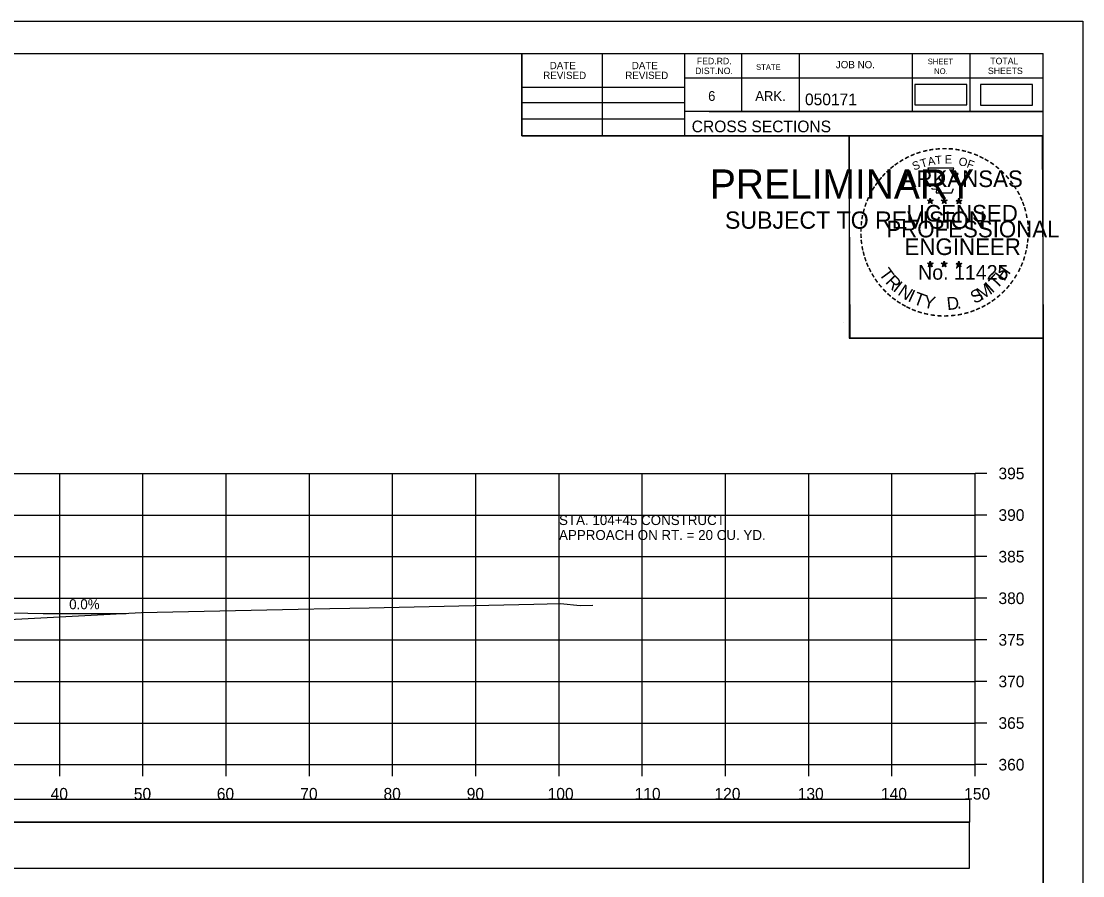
# Model space of a CAD drawing. Extents: x -37291014 to -37290680, y -936053 to -933067.
# Drawn here: x -37290807.7 to -37290680.2, y -935089.3 to -934986.6 of the extents above; entities that cross this region are included whole.
import ezdxf

# ---------------------------------------------------------------- set-up
doc = ezdxf.new("R2010")
doc.units = 0
for name, color, linetype in [('Default', 7, 'Continuous'), ('R_Axis', 7, 'Continuous'), ('R_Axis Annot', 7, 'Continuous'), ('R_Border', 7, 'Continuous'), ('R_Border PE', 7, 'Continuous'), ('R_Border Prem', 7, 'Continuous'), ('R_Drive', 7, 'Continuous'), ('R_Exist Surface', 7, 'Continuous'), ('R_Grid', 7, 'Continuous'), ('R_No Plot', 7, 'Continuous'), ('R_Water Annot', 7, 'Continuous'), ('R_Xsect Elev', 7, 'Continuous')]:
    doc.layers.add(name, color=color, linetype=linetype)

msp = doc.modelspace()

# ---------------------------------------------------------------- linework, layer by layer
at = {"layer": 'Default'}
for points in [[(-37290700.35, -934996.68), (-37290694.1, -934996.68), (-37290694.1, -934994.21), (-37290700.35, -934994.21)], [(-37290692.46, -934996.69), (-37290686.21, -934996.69), (-37290686.21, -934994.21), (-37290692.46, -934994.21)], [(-37290992.48, -935082.88), (-37290693.72, -935082.88), (-37290693.72, -935080.17), (-37290992.48, -935080.17)], [(-37290992.54, -935088.4), (-37290693.78, -935088.4), (-37290693.78, -935082.88), (-37290992.54, -935082.88)]]:
    msp.add_lwpolyline(points, close=True, dxfattribs=at)
at = {"layer": 'R_Axis'}
for p, q in [((-37290693.1, -935075.97), (-37290693.1, -935040.97)), ((-37290691.7, -935040.97), (-37290693.1, -935040.97)), ((-37290691.7, -935045.97), (-37290693.1, -935045.97)), ((-37290691.7, -935050.97), (-37290693.1, -935050.97)), ((-37290691.7, -935055.97), (-37290693.1, -935055.97)), ((-37290691.7, -935060.97), (-37290693.1, -935060.97)), ((-37290691.7, -935065.97), (-37290693.1, -935065.97)), ((-37290691.7, -935070.97), (-37290693.1, -935070.97)), ((-37290993.1, -935075.97), (-37290693.1, -935075.97)), ((-37290803.1, -935077.37), (-37290803.1, -935075.97)), ((-37290793.1, -935077.37), (-37290793.1, -935075.97)), ((-37290783.1, -935077.37), (-37290783.1, -935075.97)), ((-37290773.1, -935077.37), (-37290773.1, -935075.97)), ((-37290763.1, -935077.37), (-37290763.1, -935075.97)), ((-37290753.1, -935077.37), (-37290753.1, -935075.97)), ((-37290743.1, -935077.37), (-37290743.1, -935075.97)), ((-37290733.1, -935077.37), (-37290733.1, -935075.97)), ((-37290723.1, -935077.37), (-37290723.1, -935075.97)), ((-37290713.1, -935077.37), (-37290713.1, -935075.97)), ((-37290703.1, -935077.37), (-37290703.1, -935075.97)), ((-37290693.1, -935077.37), (-37290693.1, -935075.97)), ((-37290691.7, -935075.97), (-37290693.1, -935075.97))]:
    msp.add_line(p, q, dxfattribs=at)
at = {"layer": 'R_Border'}
for p, q in [((-37291001.1, -934990.51), (-37290684.92, -934990.51)), ((-37290747.56, -935000.39), (-37290747.56, -934990.51)), ((-37290737.88, -935000.39), (-37290737.88, -934990.51)), ((-37290728.02, -934990.51), (-37290728.02, -935000.39)), ((-37290721.18, -934990.51), (-37290721.18, -934997.45)), ((-37290714.24, -934990.51), (-37290714.24, -934997.45)), ((-37290700.66, -934990.51), (-37290700.66, -934997.45)), ((-37290693.72, -934990.51), (-37290693.72, -934997.45)), ((-37290684.92, -935195.97), (-37290684.92, -934990.51)), ((-37290747.56, -934994.53), (-37290728.02, -934994.53)), ((-37290684.92, -934993.45), (-37290728.02, -934993.45)), ((-37290684.92, -934993.43), (-37290684.92, -934993.43)), ((-37290747.56, -934996.39), (-37290728.02, -934996.39)), ((-37290747.56, -934998.33), (-37290728.02, -934998.33)), ((-37290684.92, -934997.45), (-37290728.02, -934997.45)), ((-37290725.06, -934997.45), (-37290684.92, -934997.45)), ((-37290684.92, -935000.39), (-37290747.56, -935000.39))]:
    msp.add_line(p, q, dxfattribs=at)
at = {"layer": 'R_Border PE'}
for p, q in [((-37290698.84, -935008.14), (-37290698.49, -935008.25)), ((-37290698.84, -935008.14), (-37290698.58, -935008.18)), ((-37290698.84, -935008.14), (-37290698.6, -935008.26)), ((-37290698.7, -935008.54), (-37290698.49, -935008.25)), ((-37290698.7, -935008.54), (-37290698.58, -935008.3)), ((-37290698.7, -935008.54), (-37290698.49, -935008.33)), ((-37290698.49, -935007.88), (-37290698.53, -935008.13)), ((-37290698.49, -935008.25), (-37290698.49, -935007.88)), ((-37290698.49, -935007.88), (-37290698.44, -935008.13)), ((-37290698.14, -935008.14), (-37290698.49, -935008.25)), ((-37290698.27, -935008.54), (-37290698.49, -935008.25)), ((-37290698.27, -935008.54), (-37290698.49, -935008.33)), ((-37290698.14, -935008.14), (-37290698.43, -935008.19)), ((-37290698.27, -935008.54), (-37290698.41, -935008.25)), ((-37290698.14, -935008.14), (-37290698.34, -935008.24)), ((-37290697.17, -935008.14), (-37290696.82, -935008.25)), ((-37290697.17, -935008.14), (-37290696.91, -935008.18)), ((-37290697.17, -935008.14), (-37290696.93, -935008.26)), ((-37290697.03, -935008.54), (-37290696.82, -935008.25)), ((-37290697.03, -935008.54), (-37290696.91, -935008.3)), ((-37290697.03, -935008.54), (-37290696.82, -935008.33)), ((-37290696.82, -935007.88), (-37290696.86, -935008.13)), ((-37290696.82, -935008.25), (-37290696.82, -935007.88)), ((-37290696.82, -935007.88), (-37290696.77, -935008.13)), ((-37290696.47, -935008.14), (-37290696.82, -935008.25)), ((-37290696.6, -935008.54), (-37290696.82, -935008.25)), ((-37290696.6, -935008.54), (-37290696.82, -935008.33)), ((-37290696.47, -935008.14), (-37290696.76, -935008.19)), ((-37290696.6, -935008.54), (-37290696.74, -935008.25)), ((-37290696.47, -935008.14), (-37290696.67, -935008.24)), ((-37290695.4, -935008.15), (-37290695.05, -935008.26)), ((-37290695.4, -935008.15), (-37290695.15, -935008.19)), ((-37290695.4, -935008.15), (-37290695.17, -935008.27)), ((-37290695.27, -935008.56), (-37290695.05, -935008.26)), ((-37290695.27, -935008.56), (-37290695.14, -935008.31)), ((-37290695.27, -935008.56), (-37290695.06, -935008.34)), ((-37290695.05, -935007.89), (-37290695.09, -935008.15)), ((-37290694.84, -935008.56), (-37290695.06, -935008.34)), ((-37290695.05, -935008.26), (-37290695.05, -935007.89)), ((-37290695.05, -935007.89), (-37290695, -935008.14)), ((-37290694.71, -935008.15), (-37290695.05, -935008.26)), ((-37290694.84, -935008.56), (-37290695.05, -935008.26)), ((-37290694.71, -935008.15), (-37290694.99, -935008.2)), ((-37290694.84, -935008.56), (-37290694.98, -935008.27)), ((-37290694.71, -935008.15), (-37290694.91, -935008.25)), ((-37290698.84, -935015.71), (-37290698.49, -935015.82)), ((-37290698.84, -935015.71), (-37290698.59, -935015.75)), ((-37290698.84, -935015.71), (-37290698.6, -935015.83)), ((-37290698.71, -935016.12), (-37290698.49, -935015.82)), ((-37290698.71, -935016.12), (-37290698.58, -935015.87)), ((-37290698.71, -935016.12), (-37290698.49, -935015.9)), ((-37290698.49, -935015.46), (-37290698.53, -935015.71)), ((-37290698.49, -935015.82), (-37290698.49, -935015.46)), ((-37290698.49, -935015.46), (-37290698.44, -935015.71)), ((-37290698.14, -935015.71), (-37290698.49, -935015.82)), ((-37290698.28, -935016.12), (-37290698.49, -935015.82)), ((-37290698.28, -935016.12), (-37290698.49, -935015.9)), ((-37290698.14, -935015.71), (-37290698.43, -935015.76)), ((-37290698.28, -935016.12), (-37290698.42, -935015.83)), ((-37290698.14, -935015.71), (-37290698.35, -935015.81)), ((-37290697.17, -935015.71), (-37290696.82, -935015.82)), ((-37290697.17, -935015.71), (-37290696.92, -935015.75)), ((-37290697.17, -935015.71), (-37290696.93, -935015.83)), ((-37290697.04, -935016.12), (-37290696.82, -935015.82)), ((-37290697.04, -935016.12), (-37290696.91, -935015.87)), ((-37290697.04, -935016.12), (-37290696.82, -935015.9)), ((-37290696.82, -935015.46), (-37290696.86, -935015.71)), ((-37290696.82, -935015.82), (-37290696.82, -935015.46)), ((-37290696.82, -935015.46), (-37290696.77, -935015.71)), ((-37290696.48, -935015.71), (-37290696.82, -935015.82)), ((-37290696.61, -935016.12), (-37290696.82, -935015.82)), ((-37290696.61, -935016.12), (-37290696.82, -935015.9)), ((-37290696.48, -935015.71), (-37290696.76, -935015.76)), ((-37290696.61, -935016.12), (-37290696.75, -935015.83)), ((-37290696.48, -935015.71), (-37290696.68, -935015.81)), ((-37290695.4, -935015.72), (-37290695.06, -935015.83)), ((-37290695.4, -935015.72), (-37290695.15, -935015.76)), ((-37290695.4, -935015.72), (-37290695.17, -935015.84)), ((-37290695.27, -935016.13), (-37290695.06, -935015.83)), ((-37290695.27, -935016.13), (-37290695.15, -935015.88)), ((-37290695.27, -935016.13), (-37290695.06, -935015.91)), ((-37290695.06, -935015.47), (-37290695.1, -935015.72)), ((-37290695.06, -935015.83), (-37290695.06, -935015.47)), ((-37290695.06, -935015.47), (-37290695.01, -935015.72)), ((-37290694.71, -935015.72), (-37290695.06, -935015.83)), ((-37290694.84, -935016.13), (-37290695.06, -935015.83)), ((-37290694.84, -935016.13), (-37290695.06, -935015.91)), ((-37290694.71, -935015.72), (-37290694.99, -935015.77)), ((-37290694.84, -935016.13), (-37290694.98, -935015.84)), ((-37290694.71, -935015.72), (-37290694.91, -935015.82))]:
    msp.add_line(p, q, dxfattribs=at)
for points in [[(-37290698.8, -935004.26), (-37290698.53, -935005.09)], [(-37290695.28, -935005.18), (-37290695.14, -935004.9), (-37290695.83, -935004.92), (-37290695.68, -935004.26), (-37290698.8, -935004.26)], [(-37290698.3, -935006.68), (-37290698.3, -935006.77), (-37290697.74, -935006.79), (-37290697.79, -935007.26), (-37290695.92, -935007.26), (-37290695.72, -935006.72)], [(-37290698.49, -935007.88), (-37290698.27, -935008.54), (-37290698.84, -935008.14), (-37290698.14, -935008.14), (-37290698.7, -935008.54), (-37290698.49, -935007.88)], [(-37290696.82, -935007.88), (-37290696.6, -935008.54), (-37290697.17, -935008.14), (-37290696.47, -935008.14), (-37290697.03, -935008.54), (-37290696.82, -935007.88)], [(-37290695.05, -935007.89), (-37290694.84, -935008.56), (-37290695.4, -935008.15), (-37290694.71, -935008.15), (-37290695.27, -935008.56), (-37290695.05, -935007.89)], [(-37290698.49, -935015.46), (-37290698.28, -935016.12), (-37290698.84, -935015.71), (-37290698.14, -935015.71), (-37290698.71, -935016.12), (-37290698.49, -935015.46)], [(-37290696.82, -935015.46), (-37290696.61, -935016.12), (-37290697.17, -935015.71), (-37290696.48, -935015.71), (-37290697.04, -935016.12), (-37290696.82, -935015.46)], [(-37290695.06, -935015.47), (-37290694.84, -935016.13), (-37290695.4, -935015.72), (-37290694.71, -935015.72), (-37290695.27, -935016.13), (-37290695.06, -935015.47)]]:
    msp.add_lwpolyline(points, dxfattribs=at)
for centre, radius in [((-37290698.49, -935008.25), 0.172), ((-37290698.49, -935008.25), 0.145), ((-37290698.49, -935008.25), 0.116), ((-37290698.49, -935008.25), 0.0991), ((-37290698.49, -935008.25), 0.0747), ((-37290698.49, -935008.25), 0.0495), ((-37290698.49, -935008.25), 0.0296), ((-37290696.82, -935008.25), 0.172), ((-37290696.82, -935008.25), 0.145), ((-37290696.82, -935008.25), 0.116), ((-37290696.82, -935008.25), 0.0991), ((-37290696.82, -935008.25), 0.0747), ((-37290696.82, -935008.25), 0.0495), ((-37290696.82, -935008.25), 0.0296), ((-37290695.05, -935008.26), 0.172), ((-37290695.05, -935008.26), 0.145), ((-37290695.05, -935008.26), 0.116), ((-37290695.05, -935008.26), 0.0991), ((-37290695.05, -935008.26), 0.0747), ((-37290695.05, -935008.26), 0.0495), ((-37290695.05, -935008.26), 0.0296), ((-37290698.49, -935015.82), 0.172), ((-37290698.49, -935015.82), 0.145), ((-37290698.49, -935015.82), 0.116), ((-37290698.49, -935015.82), 0.0991), ((-37290698.49, -935015.82), 0.0747), ((-37290698.49, -935015.82), 0.0495), ((-37290698.49, -935015.82), 0.0296), ((-37290696.82, -935015.82), 0.172), ((-37290696.82, -935015.82), 0.145), ((-37290696.82, -935015.82), 0.116), ((-37290696.82, -935015.82), 0.0991), ((-37290696.82, -935015.82), 0.0747), ((-37290696.82, -935015.82), 0.0495), ((-37290696.82, -935015.82), 0.0296), ((-37290695.06, -935015.83), 0.172), ((-37290695.06, -935015.83), 0.145), ((-37290695.06, -935015.83), 0.116), ((-37290695.06, -935015.83), 0.0991), ((-37290695.06, -935015.83), 0.0747), ((-37290695.06, -935015.83), 0.0495), ((-37290695.06, -935015.83), 0.0296)]:
    msp.add_circle(centre, radius, dxfattribs=at)
at = {"layer": 'R_Drive'}
for p, q in [((-37290828.1, -935057.33), (-37290805.1, -935057.79)), ((-37290805.1, -935057.79), (-37290795.1, -935057.79))]:
    msp.add_line(p, q, dxfattribs=at)
at = {"layer": 'R_Exist Surface'}
msp.add_lwpolyline([(-37290812.22, -935058.67), (-37290793.27, -935057.69), (-37290774.45, -935057.29), (-37290770.62, -935057.21), (-37290768.25, -935057.16), (-37290765.91, -935057.11), (-37290746.11, -935056.68), (-37290742.92, -935056.61), (-37290740.55, -935056.84), (-37290739.05, -935056.82)], dxfattribs=at)
at = {"layer": 'R_Grid'}
for p, q in [((-37290993.1, -935040.97), (-37290693.1, -935040.97)), ((-37290803.1, -935075.97), (-37290803.1, -935040.97)), ((-37290793.1, -935075.97), (-37290793.1, -935040.97)), ((-37290783.1, -935075.97), (-37290783.1, -935040.97)), ((-37290773.1, -935075.97), (-37290773.1, -935040.97)), ((-37290763.1, -935075.97), (-37290763.1, -935040.97)), ((-37290753.1, -935075.97), (-37290753.1, -935040.97)), ((-37290743.1, -935075.97), (-37290743.1, -935040.97)), ((-37290733.1, -935075.97), (-37290733.1, -935040.97)), ((-37290723.1, -935075.97), (-37290723.1, -935040.97)), ((-37290713.1, -935075.97), (-37290713.1, -935040.97)), ((-37290703.1, -935075.97), (-37290703.1, -935040.97)), ((-37290693.1, -935075.97), (-37290693.1, -935040.97)), ((-37290993.1, -935045.97), (-37290693.1, -935045.97)), ((-37290993.1, -935050.97), (-37290693.1, -935050.97)), ((-37290993.1, -935055.97), (-37290693.1, -935055.97)), ((-37290993.1, -935060.97), (-37290693.1, -935060.97)), ((-37290993.1, -935065.97), (-37290693.1, -935065.97)), ((-37290993.1, -935070.97), (-37290693.1, -935070.97)), ((-37290993.1, -935075.97), (-37290693.1, -935075.97))]:
    msp.add_line(p, q, dxfattribs=at)
at = {"layer": 'R_No Plot'}
for p, q in [((-37291013.5, -934986.62), (-37290680.17, -934986.62)), ((-37290708.89, -935022.85), (-37290708.89, -935022.85))]:
    msp.add_line(p, q, dxfattribs=at)
for points in [[(-37291013.51, -934986.62), (-37290680.17, -934986.62), (-37290680.17, -935199.95), (-37291013.51, -935199.95)], [(-37290767.18, -934990.51), (-37290747.56, -934990.51), (-37290747.56, -935000.39), (-37290731.45, -935000.39), (-37290708.25, -935000.39), (-37290708.25, -935024.72), (-37290684.92, -935024.72), (-37290684.92, -935195.97), (-37291001.1, -935195.97), (-37291001.1, -934990.51)], [(-37290708.25, -935000.39), (-37290685.04, -935000.39), (-37290684.92, -935024.72), (-37290708.13, -935024.72)]]:
    msp.add_lwpolyline(points, close=True, dxfattribs=at)

# ---------------------------------------------------------------- texts
at = {"layer": 'R_Axis Annot'}
for s, p in [('395', (-37290690.3, -935041.67)), ('390', (-37290690.3, -935046.67)), ('385', (-37290690.3, -935051.67)), ('380', (-37290690.3, -935056.67)), ('375', (-37290690.3, -935061.67)), ('370', (-37290690.3, -935066.67)), ('365', (-37290690.3, -935071.67)), ('360', (-37290690.3, -935076.67)), ('40', (-37290804.19, -935080.17)), ('50', (-37290794.19, -935080.17)), ('60', (-37290784.22, -935080.17)), ('70', (-37290774.19, -935080.17)), ('80', (-37290764.19, -935080.17)), ('90', (-37290754.19, -935080.17)), ('100', (-37290744.47, -935080.17)), ('110', (-37290734.02, -935080.17)), ('120', (-37290724.42, -935080.17)), ('130', (-37290714.42, -935080.17)), ('140', (-37290704.42, -935080.17)), ('150', (-37290694.42, -935080.17))]:
    msp.add_text(s, height=1.4, dxfattribs=at).set_placement(p)
at = {"layer": 'R_Border'}
for s, height, p in [('DATE', 0.879, (-37290744.22, -934992.38)), ('DATE', 0.879, (-37290734.36, -934992.38)), ('FED.RD.', 0.782, (-37290726.54, -934991.79)), ('STATE', 0.684, (-37290719.42, -934992.47)), ('JOB NO.', 0.879, (-37290709.84, -934992.27)), ('SHEET', 0.684, (-37290698.8, -934991.79)), ('TOTAL', 0.782, (-37290691.28, -934991.79)), ('REVISED', 0.879, (-37290745, -934993.56)), ('REVISED', 0.879, (-37290735.14, -934993.56)), ('DIST.NO.', 0.782, (-37290726.74, -934992.97)), ('NO.', 0.684, (-37290698.02, -934992.97)), ('SHEETS', 0.782, (-37290691.56, -934992.97)), ('6', 1.17, (-37290725.18, -934996.19)), ('ARK.', 1.172, (-37290719.52, -934996.19)), ('050171', 1.4, (-37290713.55, -934996.71)), ('CROSS SECTIONS', 1.4, (-37290727.16, -934999.96))]:
    msp.add_text(s, height=height, dxfattribs=at).set_placement(p)
at = {"layer": 'R_Border PE'}
for s, height, rotation, p in [('-', 1.6, 19.1761, (-37290700.05, -935003.13)), ('-', 1.6, 13.6302, (-37290699.3, -935002.89)), ('-', 1.6, 10.2193, (-37290698.62, -935002.73)), ('-', 1.6, 5.8968, (-37290697.89, -935002.62)), ('-', 1.6, 0.1862, (-37290697.12, -935002.55)), ('-', 1.6, 357.743, (-37290696.4, -935002.56)), ('-', 1.6, 352.1617, (-37290695.65, -935002.62)), ('-', 1.6, 347.2049, (-37290694.93, -935002.73)), ('-', 1.6, 342.3362, (-37290694.3, -935002.88)), ('-', 1.6, 36.2317, (-37290702.49, -935004.48)), ('-', 1.6, 34.0636, (-37290701.91, -935004.09)), ('-', 1.6, 28.7918, (-37290701.31, -935003.72)), ('-', 1.6, 24.3072, (-37290700.68, -935003.4)), ('S', 1, 21.594, (-37290700.44, -935004.58)), ('T', 1, 16.4036, (-37290699.53, -935004.25)), ('A', 1, 11.2132, (-37290698.7, -935004)), ('T', 1, 6.0228, (-37290697.85, -935003.83)), ('E', 1, 0.8323, (-37290696.75, -935003.72)), ('O', 1, 350.4515, (-37290695.14, -935003.93)), ('F', 1, 340.0707, (-37290694.19, -935004.16)), ('-', 1.6, 337.8551, (-37290693.56, -935003.11)), ('-', 1.6, 334.1211, (-37290692.93, -935003.38)), ('-', 1.6, 329.6409, (-37290692.35, -935003.66)), ('-', 1.6, 325.8627, (-37290691.71, -935004.02)), ('-', 1.6, 48.4231, (-37290703.85, -935005.76)), ('-', 1.6, 42.9622, (-37290703.4, -935005.28)), ('-', 1.6, 38.9507, (-37290702.97, -935004.86)), ('-', 1.6, 320.5297, (-37290691.1, -935004.45)), ('-', 1.6, 315.5786, (-37290690.5, -935004.94)), ('-', 1.6, 54.2325, (-37290704.66, -935006.81)), ('-', 1.6, 50.6142, (-37290704.25, -935006.24)), ('-', 1.6, 309.8797, (-37290689.93, -935005.49)), ('-', 1.6, 306.6522, (-37290689.41, -935006.09)), ('-', 1.6, 62.8713, (-37290705.3, -935007.95)), ('-', 1.6, 58.0706, (-37290704.99, -935007.34)), ('-', 1.4, 303.6753, (-37290688.92, -935006.66)), ('-', 1.6, 299.6684, (-37290688.6, -935007.26)), ('-', 1.6, 72.3945, (-37290705.78, -935009.19)), ('-', 1.6, 67.7743, (-37290705.56, -935008.56)), ('-', 1.6, 294.6628, (-37290688.28, -935007.88)), ('-', 1.6, 290.5728, (-37290688.02, -935008.45)), ('-', 1.6, 81.2013, (-37290706.11, -935010.62)), ('-', 1.6, 75.461, (-37290705.98, -935009.9)), ('-', 1.6, 285.1233, (-37290687.79, -935009.03)), ('-', 1.6, 280.5493, (-37290687.59, -935009.77)), ('-', 1.6, 85.1863, (-37290706.18, -935011.31)), ('-', 1.6, 276.5962, (-37290687.42, -935010.54)), ('-', 1.6, 94.1959, (-37290706.17, -935012.73)), ('-', 1.6, 89.0622, (-37290706.21, -935012.01)), ('-', 1.6, 274.3301, (-37290687.36, -935011.26)), ('-', 1.6, 269.9407, (-37290687.33, -935011.9)), ('-', 1.6, 98.9479, (-37290706.1, -935013.4)), ('-', 1.6, 101.7149, (-37290705.97, -935014.13)), ('-', 1.6, 260.9953, (-37290687.42, -935013.22)), ('-', 1.6, 263.5172, (-37290687.35, -935012.56)), ('-', 1.6, 105.4578, (-37290705.8, -935014.73)), ('-', 1.6, 109.0874, (-37290705.59, -935015.36)), ('-', 1.6, 252.8681, (-37290687.71, -935014.61)), ('-', 1.6, 255.7626, (-37290687.53, -935013.89)), ('-', 1.6, 114.0643, (-37290705.34, -935015.96)), ('-', 1.6, 115.7289, (-37290705.03, -935016.57)), ('T', 1.54, 306.0406, (-37290704.73, -935016.98)), ('H', 1.54, 54.6088, (-37290689.61, -935017.95)), ('-', 1.6, 244.6197, (-37290688.2, -935015.92)), ('-', 1.6, 247.8887, (-37290687.93, -935015.29)), ('-', 1.6, 120.4471, (-37290704.67, -935017.16)), ('-', 1.6, 125.8934, (-37290704.27, -935017.72)), ('R', 1.54, 314.005, (-37290703.97, -935018.03)), ('T', 1.54, 46.6444, (-37290690.5, -935018.89)), ('-', 1.6, 239.0712, (-37290688.59, -935016.67)), ('-', 1.6, 130.7181, (-37290703.81, -935018.27)), ('-', 1.6, 134.2238, (-37290703.29, -935018.82)), ('I', 1.54, 321.9694, (-37290703.07, -935018.96)), ('N', 1.54, 326.5002, (-37290702.5, -935019.43)), ('S', 1.54, 26.9312, (-37290693.19, -935020.62)), ('M', 1.54, 32.6563, (-37290692.35, -935020.21)), ('I', 1.54, 42.1136, (-37290691.06, -935019.37)), ('-', 1.6, 231.2538, (-37290689.42, -935017.89)), ('-', 1.6, 233.8452, (-37290688.99, -935017.32)), ('-', 1.6, 138.9338, (-37290702.77, -935019.28)), ('-', 1.6, 144.6463, (-37290702.21, -935019.69)), ('I', 1.54, 335.3603, (-37290701.29, -935020.22)), ('T', 1.54, 339.8912, (-37290700.63, -935020.55)), ('Y', 1.54, 347.8556, (-37290699.42, -935020.99)), ('D', 1.54, 6.3969, (-37290696.43, -935021.35)), ('-', 1.6, 215.7363, (-37290690.97, -935019.43)), ('-', 1.6, 221.0851, (-37290690.42, -935018.96)), ('-', 1.6, 225.7653, (-37290689.9, -935018.45)), ('-', 1.6, 148.0898, (-37290701.65, -935020.06)), ('-', 1.6, 151.5704, (-37290701.07, -935020.38)), ('-', 1.6, 154.6002, (-37290700.55, -935020.63)), ('-', 1.6, 158.5612, (-37290699.92, -935020.89)), ('.', 1.54, 13.7642, (-37290695.24, -935021.22)), ('-', 1.6, 200.7184, (-37290693.31, -935020.76)), ('-', 1.6, 204.2516, (-37290692.69, -935020.48)), ('-', 1.6, 207.3568, (-37290692.06, -935020.17)), ('-', 1.6, 212.2491, (-37290691.51, -935019.82)), ('-', 1.6, 162.7983, (-37290699.24, -935021.1)), ('-', 1.6, 167.5555, (-37290698.52, -935021.26)), ('-', 1.6, 173.1155, (-37290697.75, -935021.37)), ('-', 1.6, 176.5183, (-37290697, -935021.43)), ('-', 1.6, 181.5918, (-37290696.26, -935021.41)), ('-', 1.6, 185.8167, (-37290695.45, -935021.33)), ('-', 1.6, 191.2858, (-37290694.71, -935021.2)), ('-', 1.6, 195.4743, (-37290693.98, -935021))]:
    msp.add_text(s, height=height, rotation=rotation, dxfattribs=at).set_placement(p)
for s, height, p in [('ARKANSAS', 2, (-37290701.94, -935006.55)), ('DWB', 0.01, (-37290698.5, -935008.25)), ('DWB', 0.01, (-37290696.83, -935008.25)), ('DWB', 0.01, (-37290695.07, -935008.26)), ('LICENSED', 2, (-37290701.35, -935010.7)), ('PROFESSIONAL', 2, (-37290703.77, -935012.6)), ('ENGINEER', 2, (-37290701.58, -935014.72)), ('No. 11425', 1.757, (-37290699.95, -935017.68)), ('DWB', 0.01, (-37290698.5, -935015.83)), ('DWB', 0.01, (-37290696.84, -935015.83)), ('DWB', 0.01, (-37290695.07, -935015.84))]:
    msp.add_text(s, height=height, dxfattribs=at).set_placement(p)
at = {"layer": 'R_Border Prem'}
for s, height, p in [('PRELIMINARY', 3.5, (-37290724.97, -935007.93)), ('DWB', 0.01, (-37290724.22, -935006.08)), ('SUBJECT TO REVISION', 2.0751, (-37290723.16, -935011.56))]:
    msp.add_text(s, height=height, dxfattribs=at).set_placement(p)
at = {"layer": 'R_Water Annot'}
for s, p in [('STA. 104+45 CONSTRUCT', (-37290743.1, -935047.17)), ('APPROACH ON RT. = 20 CU. YD.', (-37290743.1, -935048.97))]:
    msp.add_text(s, height=1.2, dxfattribs=at).set_placement(p)
at = {"layer": 'R_Xsect Elev'}
msp.add_text('0.0%', height=1.2, rotation=0.008, dxfattribs=at).set_placement((-37290801.96, -935057.29))

doc.saveas('drawing.dxf')
